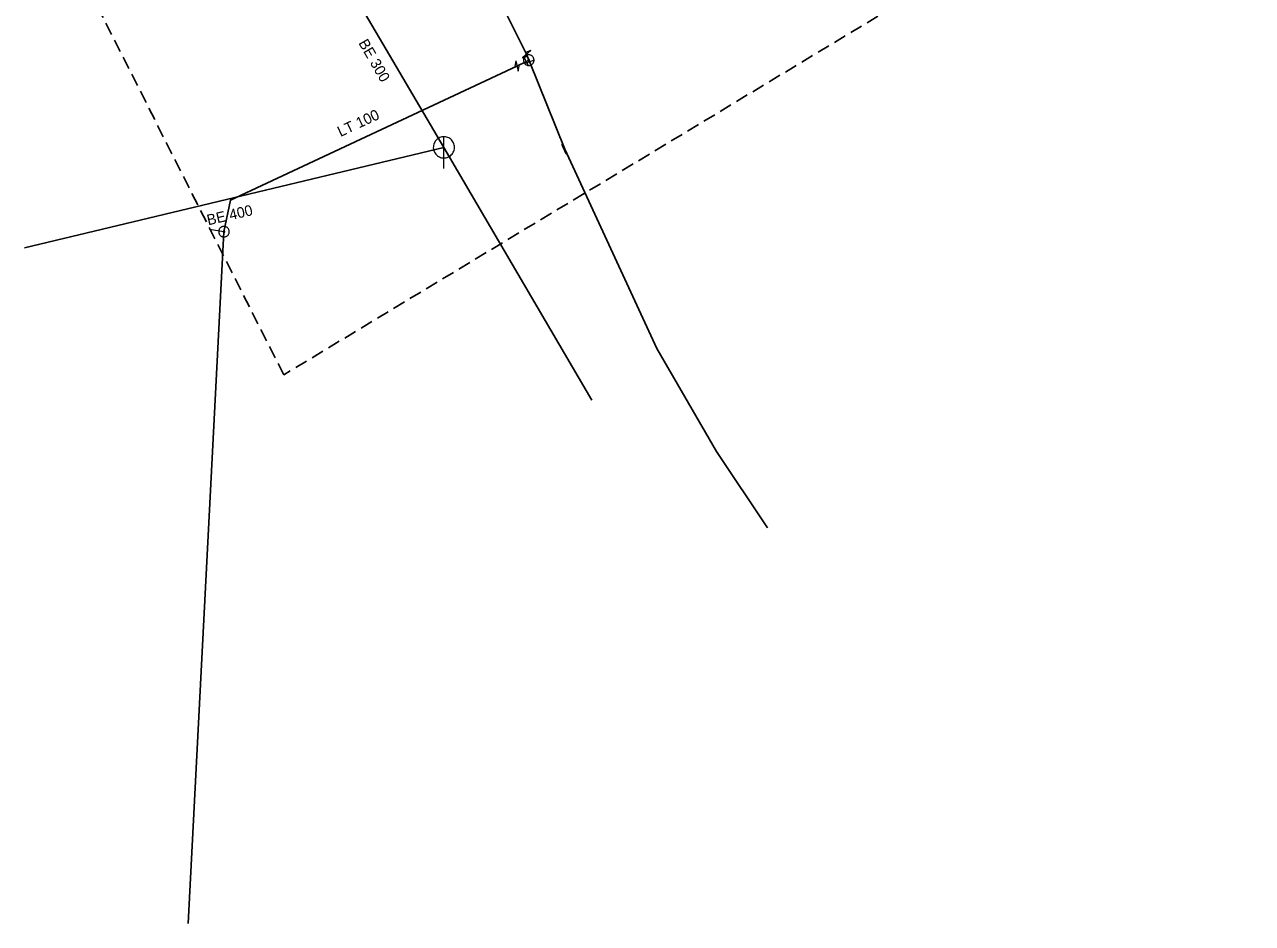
# Model space of a CAD drawing. Extents: x -689189 to -688666, y -973229 to -972850.
# Drawn here: x -689188.5 to -689072.6, y -973229.3 to -973144.4 of the extents above; entities that cross this region are included whole.
import ezdxf

# ---------------------------------------------------------------- set-up
doc = ezdxf.new("R2010")
doc.units = 0
doc.header["$LTSCALE"] = 0.4
doc.linetypes.add('MEDIUM_DASHED', pattern=[4.5, 3, -1.5])
doc.layers.add('1', color=7, linetype='Continuous')
for name, color, linetype, lineweight in [('14', 7, 'Continuous', 13), ('17', 7, 'Continuous', 25), ('22', 7, 'Continuous', 13), ('34', 7, 'Continuous', 13), ('47', 7, 'Continuous', 13), ('63', 7, 'MEDIUM_DASHED', 25)]:
    doc.layers.add(name, color=color, linetype=linetype, lineweight=lineweight)

msp = doc.modelspace()

# ---------------------------------------------------------------- linework, layer by layer
at = {"layer": '14', "lineweight": 25}
for p, q in [((-689158.682, -973139.478), (-689148.953, -973156.032)), ((-689188.54, -973165.513), (-689148.953, -973156.032)), ((-689148.953, -973156.032), (-689134.999, -973179.901))]:
    msp.add_line(p, q, dxfattribs=at)
at = {"layer": '14'}
for p, q in [((-689137.55, -973156.199), (-689137.616, -973156.229)), ((-689169.716, -973163.999), (-689171.095, -973163.775))]:
    msp.add_line(p, q, dxfattribs=at)
msp.add_lwpolyline([(-689140.879, -973147.94), (-689140.94, -973147.8), (-689141.17, -973147.92)], dxfattribs=at)
at = {"layer": '17'}
for p, q in [((-689145.719, -973138.12), (-689141.14, -973147.239)), ((-689140.94, -973147.8), (-689141.14, -973147.239)), ((-689141.17, -973147.92), (-689142.052, -973148.352)), ((-689169.716, -973163.999), (-689173.097, -973229.322))]:
    msp.add_line(p, q, dxfattribs=at)
for points in [[(-689142.052, -973148.352), (-689169.112, -973161.017), (-689169.716, -973163.999)], [(-689118.399, -973191.969), (-689123.219, -973184.75), (-689128.859, -973175.039), (-689137.55, -973156.199), (-689140.879, -973147.94)]]:
    msp.add_lwpolyline(points, dxfattribs=at)
at = {"layer": '22'}
msp.add_line((-689148.953, -973158.032), (-689148.952, -973155.032), dxfattribs=at)
msp.add_lwpolyline([(-689147.953, -973156.032), (-689147.958, -973155.923), (-689147.976, -973155.815), (-689148.006, -973155.709), (-689148.046, -973155.608), (-689148.098, -973155.511), (-689148.16, -973155.421), (-689148.232, -973155.338), (-689148.312, -973155.264), (-689148.4, -973155.198), (-689148.494, -973155.143), (-689148.594, -973155.098), (-689148.699, -973155.065), (-689148.806, -973155.043), (-689148.915, -973155.033), (-689149.025, -973155.035), (-689149.133, -973155.049), (-689149.24, -973155.074), (-689149.343, -973155.111), (-689149.441, -973155.16), (-689149.533, -973155.218), (-689149.619, -973155.287), (-689149.696, -973155.364), (-689149.765, -973155.45), (-689149.824, -973155.542), (-689149.872, -973155.64), (-689149.909, -973155.743), (-689149.935, -973155.85), (-689149.949, -973155.958), (-689149.952, -973156.068), (-689149.942, -973156.177), (-689149.921, -973156.284), (-689149.887, -973156.388), (-689149.843, -973156.488), (-689149.788, -973156.583), (-689149.722, -973156.671), (-689149.648, -973156.751), (-689149.565, -973156.823), (-689149.475, -973156.885), (-689149.379, -973156.937), (-689149.277, -973156.978), (-689149.172, -973157.008), (-689149.064, -973157.026), (-689148.954, -973157.032), (-689148.845, -973157.026), (-689148.737, -973157.008), (-689148.632, -973156.979), (-689148.53, -973156.938), (-689148.433, -973156.886), (-689148.343, -973156.824), (-689148.26, -973156.753), (-689148.185, -973156.673), (-689148.12, -973156.585), (-689148.064, -973156.491), (-689148.02, -973156.391), (-689147.986, -973156.287), (-689147.964, -973156.179), (-689147.954, -973156.07)], close=True, dxfattribs=at)
at = {"layer": '34'}
for p, q in [((-689140.938, -973148.363), (-689141.4, -973147.476)), ((-689141.342, -973148.127), (-689140.415, -973147.753)), ((-689137.414, -973156.686), (-689137.816, -973155.77))]:
    msp.add_line(p, q, dxfattribs=at)
at = {"layer": '47'}
for p, q in [((-689140.76, -973146.899), (-689141.242, -973147.066)), ((-689142.15, -973147.852), (-689142.253, -973148.352))]:
    msp.add_line(p, q, dxfattribs=at)
for points in [[(-689140.76, -973146.899), (-689141.519, -973147.578), (-689141.037, -973147.411)], [(-689142.15, -973147.852), (-689141.954, -973148.852), (-689141.851, -973148.352)]]:
    msp.add_lwpolyline(points, dxfattribs=at)
for points in [[(-689141.136, -973147.34), (-689141.183, -973147.363), (-689141.228, -973147.391), (-689141.268, -973147.424), (-689141.306, -973147.459), (-689141.34, -973147.5), (-689141.369, -973147.544), (-689141.393, -973147.59), (-689141.412, -973147.639), (-689141.427, -973147.688), (-689141.436, -973147.74), (-689141.44, -973147.793), (-689141.437, -973147.845), (-689141.43, -973147.897), (-689141.417, -973147.947), (-689141.399, -973147.996), (-689141.376, -973148.043), (-689141.348, -973148.088), (-689141.315, -973148.129), (-689141.28, -973148.166), (-689141.239, -973148.2), (-689141.195, -973148.229), (-689141.149, -973148.254), (-689141.1, -973148.273), (-689141.05, -973148.288), (-689140.999, -973148.296), (-689140.946, -973148.3), (-689140.894, -973148.298), (-689140.842, -973148.29), (-689140.792, -973148.277), (-689140.743, -973148.259), (-689140.696, -973148.236), (-689140.651, -973148.208), (-689140.61, -973148.176), (-689140.573, -973148.14), (-689140.539, -973148.099), (-689140.51, -973148.056), (-689140.485, -973148.009), (-689140.466, -973147.961), (-689140.451, -973147.91), (-689140.443, -973147.859), (-689140.439, -973147.806), (-689140.441, -973147.754), (-689140.449, -973147.702), (-689140.462, -973147.652), (-689140.48, -973147.603), (-689140.503, -973147.556), (-689140.531, -973147.511), (-689140.563, -973147.47), (-689140.599, -973147.433), (-689140.64, -973147.399), (-689140.683, -973147.37), (-689140.729, -973147.346), (-689140.778, -973147.327), (-689140.828, -973147.312), (-689140.88, -973147.303), (-689140.933, -973147.299), (-689140.984, -973147.302), (-689141.037, -973147.309), (-689141.087, -973147.322)], [(-689140.972, -973147.724), (-689140.98, -973147.728), (-689140.987, -973147.733), (-689140.993, -973147.738), (-689140.999, -973147.744), (-689141.005, -973147.75), (-689141.01, -973147.758), (-689141.014, -973147.765), (-689141.017, -973147.773), (-689141.019, -973147.781), (-689141.021, -973147.79), (-689141.021, -973147.799), (-689141.021, -973147.807), (-689141.02, -973147.815), (-689141.018, -973147.824), (-689141.015, -973147.832), (-689141.011, -973147.84), (-689141.006, -973147.847), (-689141.001, -973147.853), (-689140.995, -973147.859), (-689140.989, -973147.865), (-689140.981, -973147.87), (-689140.974, -973147.874), (-689140.966, -973147.877), (-689140.957, -973147.88), (-689140.949, -973147.881), (-689140.94, -973147.881), (-689140.932, -973147.881), (-689140.924, -973147.88), (-689140.915, -973147.878), (-689140.907, -973147.875), (-689140.899, -973147.871), (-689140.892, -973147.866), (-689140.886, -973147.861), (-689140.88, -973147.855), (-689140.874, -973147.849), (-689140.869, -973147.842), (-689140.865, -973147.834), (-689140.862, -973147.826), (-689140.859, -973147.817), (-689140.858, -973147.809), (-689140.858, -973147.8), (-689140.858, -973147.792), (-689140.859, -973147.784), (-689140.861, -973147.775), (-689140.864, -973147.767), (-689140.868, -973147.759), (-689140.873, -973147.752), (-689140.878, -973147.746), (-689140.884, -973147.74), (-689140.89, -973147.734), (-689140.897, -973147.729), (-689140.905, -973147.725), (-689140.913, -973147.722), (-689140.921, -973147.72), (-689140.93, -973147.718), (-689140.939, -973147.718), (-689140.947, -973147.718), (-689140.955, -973147.719), (-689140.964, -973147.721)], [(-689169.633, -973163.505), (-689169.684, -973163.5), (-689169.737, -973163.499), (-689169.789, -973163.505), (-689169.84, -973163.514), (-689169.89, -973163.53), (-689169.939, -973163.551), (-689169.983, -973163.577), (-689170.026, -973163.608), (-689170.065, -973163.642), (-689170.101, -973163.68), (-689170.133, -973163.723), (-689170.158, -973163.768), (-689170.181, -973163.815), (-689170.197, -973163.865), (-689170.209, -973163.916), (-689170.214, -973163.967), (-689170.215, -973164.02), (-689170.21, -973164.073), (-689170.2, -973164.123), (-689170.184, -973164.173), (-689170.163, -973164.222), (-689170.137, -973164.267), (-689170.107, -973164.31), (-689170.073, -973164.349), (-689170.034, -973164.384), (-689169.991, -973164.416), (-689169.946, -973164.442), (-689169.899, -973164.464), (-689169.849, -973164.48), (-689169.798, -973164.492), (-689169.747, -973164.497), (-689169.694, -973164.498), (-689169.642, -973164.494), (-689169.591, -973164.483), (-689169.541, -973164.467), (-689169.493, -973164.447), (-689169.447, -973164.421), (-689169.404, -973164.391), (-689169.365, -973164.356), (-689169.33, -973164.317), (-689169.298, -973164.274), (-689169.272, -973164.23), (-689169.25, -973164.182), (-689169.234, -973164.132), (-689169.222, -973164.081), (-689169.217, -973164.03), (-689169.216, -973163.977), (-689169.221, -973163.925), (-689169.231, -973163.874), (-689169.247, -973163.824), (-689169.267, -973163.776), (-689169.293, -973163.731), (-689169.324, -973163.688), (-689169.359, -973163.649), (-689169.397, -973163.613), (-689169.44, -973163.581), (-689169.484, -973163.556), (-689169.532, -973163.533), (-689169.582, -973163.517)], [(-689169.702, -973163.918), (-689169.711, -973163.916), (-689169.719, -973163.917), (-689169.727, -973163.917), (-689169.736, -973163.919), (-689169.744, -973163.922), (-689169.752, -973163.925), (-689169.76, -973163.929), (-689169.767, -973163.934), (-689169.773, -973163.94), (-689169.779, -973163.946), (-689169.784, -973163.954), (-689169.788, -973163.961), (-689169.792, -973163.968), (-689169.795, -973163.976), (-689169.796, -973163.985), (-689169.798, -973163.994), (-689169.797, -973164.002), (-689169.797, -973164.01), (-689169.795, -973164.019), (-689169.792, -973164.027), (-689169.789, -973164.035), (-689169.785, -973164.043), (-689169.78, -973164.05), (-689169.774, -973164.057), (-689169.768, -973164.062), (-689169.76, -973164.067), (-689169.753, -973164.071), (-689169.746, -973164.075), (-689169.738, -973164.078), (-689169.729, -973164.079), (-689169.72, -973164.081), (-689169.712, -973164.08), (-689169.704, -973164.08), (-689169.695, -973164.078), (-689169.687, -973164.075), (-689169.679, -973164.073), (-689169.671, -973164.068), (-689169.664, -973164.063), (-689169.657, -973164.057), (-689169.652, -973164.051), (-689169.647, -973164.043), (-689169.643, -973164.036), (-689169.639, -973164.029), (-689169.636, -973164.021), (-689169.635, -973164.012), (-689169.633, -973164.003), (-689169.634, -973163.995), (-689169.634, -973163.987), (-689169.636, -973163.978), (-689169.639, -973163.97), (-689169.641, -973163.962), (-689169.646, -973163.954), (-689169.651, -973163.947), (-689169.657, -973163.941), (-689169.663, -973163.935), (-689169.671, -973163.93), (-689169.678, -973163.926), (-689169.685, -973163.922), (-689169.693, -973163.919)]]:
    msp.add_lwpolyline(points, close=True, dxfattribs=at)
at = {"layer": '63'}
msp.add_lwpolyline([(-689164.065, -973177.51), (-689187.511, -973131.176), (-688767.155, -972886.107), (-688767.155, -972886.107), (-688777.761, -972958.121), (-688777.761, -972958.121), (-688989.335, -973072.002), (-688989.335, -973072.002)], close=True, dxfattribs=at)

# ---------------------------------------------------------------- texts
at = {"layer": '1'}
for s, rotation, p in [('BE 300', 300, (-689157.048, -973146.173)), ('LT 100', 25, (-689158.716, -973155.063)), ('BE 400', 13, (-689171.202, -973163.401))]:
    msp.add_text(s, height=1, rotation=rotation, dxfattribs=at).set_placement(p)

doc.saveas('drawing.dxf')
